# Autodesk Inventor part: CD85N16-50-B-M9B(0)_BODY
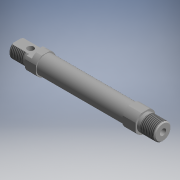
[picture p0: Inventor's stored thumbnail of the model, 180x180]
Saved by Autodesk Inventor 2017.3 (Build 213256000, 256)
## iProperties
Part Number: CD85N16-50-B-M9B(0)_BODY
Material: Generic
Catalog Web Link: www.cadenas.de
Description: C85/CD85 BODY-ISO Standard Air Cylinder:Standard Type Double Acting Single Rod
Vendor: SMC
Document SubType Name: Modeling
Designer: partserver
Manufacturer: SMC
Mass: 19.9773 g
Surface Area: 122.047 cm^2
Volume: 19.9773 cm^3
Density: 1 g/cm^3
Appearance: PSOLRGB-192-192-192
Category: PARTsolutions
Company: SMC
Title: CD85N16-50-B-M9B_BODY
Author: Cadenas PARTsolutions
Comments: ISO Standard Air Cylinder:Standard Type Double Acting Single Rod
PSOL_IDENT_0: {$CADENAS_DATA\23d-libs\smc_jp\actuator\standard_air_cylinder\c85\c85\parts\c85_body.prj},247 {VTYP=
PSOL_IDENT_1: 3D},{NB=CD85N16-50-B-M9B(0)_BODY},{LINA=CD85N16-50-B-M9B_BODY},{NN=C85/CD85 BODY},{DATE=09.12.2020 0
PSOL_IDENT_2: 3:32:12},{GEOMDATE=26.04.2020 06:36:00},{VERSION=},{LINEID=90},{WBVAR=MAGNET,AUTOSW,STROKE,CUSHION,B
PSOL_IDENT_3: OOT,SWITCHMT,THREAD},{WBNUMERIC=STROKE}  {NB=CD85N16-50-B-M9B(0)_BODY},{LINA=CD85N16-50-B-M9B_BODY},
PSOL_IDENT_4: {KT=DUMMY},{ORDER=CD85N16-50-B-M9B},{BORE=16},{MOUNT=(N) Basic (Integral clevis)},{MOUNTX=N},{MAGNET=
PSOL_IDENT_5: D},{AUTOSW=-M9B},{AUTOSWX='','(-) Without auto switch','-M9N','M9N','-M9P','M9P','-M9B','M9B','-M9NV'
PSOL_IDENT_6: ,'M9NV','-M9PV','M9PV','-M9BV','M9BV','-M9NW','M9NW','-M9PW','M9PW','-M9BW','M9BW','-M9NWV','M9NWV','
PSOL_IDENT_7: -M9PWV','M9PWV','-M9BWV','M9BWV','-M9NA','M9NA','-M9PA','M9PA','-M9BA','M9BA','-M9NAV','M9NAV','-M9P
PSOL_IDENT_8: AV','M9PAV','-M9BAV','M9BAV','-A90','A90','-A93','A93','-A96','A96','-A90V','A90V','-A93V','A93V','-
PSOL_IDENT_9: A96V','A96V','-H7C','H7C','-H7NF','H7NF','-C73C','C73C','-C80C','C80C','-J79C','J79C','-F79F','F79F'
PSOL_IDENT_10: ,'-A72','A72','-A72H','A72H','-A73C','A73C','-A80C','A80C','-A79W','A79W'},{STROKE=50},{CUSHION=},{C
PSOL_IDENT_11: USHIONX= '','(-) Rubber bumper(Standard)','C','(C) Air cushion' },{BOOT=},{BOOTX= '','N/A' },{SWITCH
PSOL_IDENT_12: MT=-B},{SWITCHMTX= '-A','(A) Rail mounting','-B','(B) Band mounting' },{THREAD=0},{MAX=400},{MAX1=20
PSOL_IDENT_13: 0},{AM=16},{BE=M16x1.5},{BED=16},{BEJ=1.50},{C=6},{CD=6},{D=19.7},{EE=M5x0.8},{EW=12},{F=17},{G1=8},
PSOL_IDENT_14: {G2=6},{HR=14.0},{N1=12.5},{N2=10.5},{NA=18.3},{ND=16},{RR=13},{S=56},{U=9},{WA=9.5},{D1=17.400},{SW
PSOL_IDENT_15: A=7.5},{SWB=13.5},{SW=2}
NB: CD85N16-50-B-M9B(0)_BODY
NN: C85/CD85 BODY
NT: ISO Standard Air Cylinder:Standard Type Double Acting Single Rod
NBSYN: $ORDER.($THREAD.)_BODY
LINA: CD85N16-50-B-M9B_BODY
CATALOG: SMC (JP
BORE: 16
MOUNT: (N) Basic (Integral clevis)
MAGNET: (D) With magnet
AUTOSW: M9B
STROKE: 50
CUSHION: (-) Rubber bumper(Standard)
BOOT: N/A
SWITCHMT: (B) Band mounting
THREAD: on
MAX: 400
MAX1: 200
AM: 16
BE: M16x1.5
BED: 16
BEJ: 1.5
C: 6
CD: 6
D: 19.7
EE: M5x0.8
EW: 12
F: 17
HR: 14
NA: 18.3
ND: 16
RR: 13
U: 9
WA: 9.5
D1: 17.4
SUPPLIER: SMC
ARTICLENO: CD85N16-50-B-M9B(0)_BODY
BOMINFO: CD85N16-50-B-M9B_BODY
CREATOR: CADENAS GmbH
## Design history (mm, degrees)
sketch "Sketch_1"
  geometry: L1 (106, 0)-(-17, 0); L2 (67.5, 0)-(67.5, 8); L3 (67.5, 8)-(12.5, 8); L4 (12.5, 8)-(12.5, 3); L5 (12.5, 3)-(-17, 3); L6 (-17, 3)-(-17, 7.08); L7 (-17, 7.08)-(-16.08, 8); L8 (-16.08, 8)-(0, 8); L9 (0, 8)-(0, 9.85); L10 (0, 9.85)-(12.5, 9.85); L11 (12.5, 9.85)-(12.5, 8.7); L12 (12.5, 8.7)-(95.5, 8.7); L13 (95.5, 8.7)-(95.5, 9.85); L14 (95.5, 9.85)-(106, 9.85); L15 (106, 9.85)-(106, 0); L16 (106, 0)-(67.5, 0)
  constraints: 32 end point
revolve "Revolution1" sketch "Sketch_1" stored, may be unused: angle "d0" = 360 deg
thread "Thread1" dims "d1" = 13.08, "d2" = 0
sketch "Sketch_2"
  geometry: L1 (3.647, 9.15)-(-3.647, 9.15); L2 (-9.15, 3.647)-(-9.15, -3.647); L3 (-3.647, -9.15)-(3.647, -9.15); L4 (9.15, -3.647)-(9.15, 3.647); C1 r 13.133 at (0, 0); A1 r 9.85 centre (0, 0) between (-3.647, 9.15) and (-9.15, 3.647); A2 r 9.85 centre (0, 0) between (-9.15, -3.647) and (-3.647, -9.15); A3 r 9.85 centre (0, 0) between (3.647, -9.15) and (9.15, -3.647); A4 r 9.85 centre (0, 0) between (9.15, 3.647) and (3.647, 9.15); 1 further point
  constraints: 8 end point, 8 point on circle, 5 centre point
extrude "Extrusion1" cut sketch "Sketch_2" distance "d3" = 111; taper "d4" = 0 deg
sketch "Sketch_3"
  geometry: L1 (8, 4.15)-(8, 9.15); L2 (8, 9.15)-(10.5, 9.15); L3 (10.5, 9.15)-(10.067, 8.717); L4 (10.067, 8.717)-(10.067, 4.15); L5 (10.067, 4.15)-(8, 2.957); L6 (8, 2.957)-(8, 9.15)
  constraints: 12 end point
revolve "Revolution2" sketch "Sketch_3" stored, may be unused: angle "d5" = 360 deg
thread "Thread2" dims "d6" = 4.567, "d7" = 0
sketch "Sketch_5"
  geometry: L1 (100, 4.15)-(100, 9.15); L2 (100, 9.15)-(102.5, 9.15); L3 (102.5, 9.15)-(102.067, 8.717); L4 (102.067, 8.717)-(102.067, 4.15); L5 (102.067, 4.15)-(100, 2.957); L6 (100, 2.957)-(100, 9.15)
  constraints: 12 end point
revolve "Revolution3" sketch "Sketch_5" stored, may be unused: angle "d8" = 360 deg
thread "Thread3" dims "d9" = 4.567, "d10" = 0
sketch "Sketch_13"
  geometry: L1 (123, 0)-(106, 0); L2 (106, 0)-(106, 8); L3 (106, 8)-(122.08, 8); L4 (122.08, 8)-(123, 7.08); L5 (123, 7.08)-(123, 0); L6 (123, 0)-(106, 0)
  constraints: 12 end point
revolve "Revolution4" sketch "Sketch_13" stored, may be unused: angle "d11" = 360 deg
thread "Thread4" dims "d12" = 13.08, "d13" = 0
sketch "Sketch_14"
  geometry: L1 (-101, -9.85)-(-101, -6); L2 (-101, -6)-(-123, -6); L3 (-123, -6)-(-123, 6); L4 (-123, 6)-(-101, 6); L5 (-101, 6)-(-101, 9.85); L6 (-101, 9.85)-(-128, 9.85); L7 (-128, 9.85)-(-128, -9.85); L8 (-128, -9.85)-(-101, -9.85)
  constraints: 16 end point
extrude "Extrusion2" cut sketch "Sketch_14" stored distance "d14" = 19.7; taper "d15" = 0 deg
sketch "Sketch_15"
  geometry: C1 r 3 at (110, 0); 1 further point
  constraints: 1 centre point
extrude "Extrusion3" cut sketch "Sketch_15" stored distance "d16" = 19.7; taper "d17" = 0 deg
node "BODY_XY"
node "BODY_YZ"
node "BODY_ZX"
node "BODY_X"
node "BODY_Y"
node "BODY_Z"
node "BODY_Center"
node "BODY_MNUT_XY"
node "BODY_MNUT_YZ"
node "BODY_MNUT_ZX"
node "BODY_MNUT_X"
node "BODY_MNUT_Y"
node "BODY_MNUT_Z"
node "BODY_MNUT_Center"
node "BODY_MNUT2_XY"
node "BODY_MNUT2_YZ"
node "BODY_MNUT2_ZX"
node "BODY_MNUT2_X"
node "BODY_MNUT2_Y"
node "BODY_MNUT2_Z"
node "BODY_MNUT2_Center"
node "Body_Bracket1_XY"
node "Body_Bracket1_YZ"
node "Body_Bracket1_ZX"
node "Body_Bracket1_X"
node "Body_Bracket1_Y"
node "Body_Bracket1_Z"
node "Body_Bracket1_Center"
node "Body_Bracket2_XY"
node "Body_Bracket2_YZ"
node "Body_Bracket2_ZX"
node "Body_Bracket2_X"
node "Body_Bracket2_Y"
node "Body_Bracket2_Z"
node "Body_Bracket2_Center"
node "Body_Clevis_XY"
node "Body_Clevis_YZ"
node "Body_Clevis_ZX"
node "Body_Clevis_X"
node "Body_Clevis_Y"
node "Body_Clevis_Z"
node "Body_Clevis_Center"
node "Body_SMA_Rail1_XY"
node "Body_SMA_Rail1_YZ"
node "Body_SMA_Rail1_ZX"
node "Body_SMA_Rail1_X"
node "Body_SMA_Rail1_Y"
node "Body_SMA_Rail1_Z"
node "Body_SMA_Rail1_Center"
node "Body_SMB_Rail2_XY"
node "Body_SMB_Rail2_YZ"
node "Body_SMB_Rail2_ZX"
node "Body_SMB_Rail2_X"
node "Body_SMB_Rail2_Y"
node "Body_SMB_Rail2_Z"
node "Body_SMB_Rail2_Center"
node "Body_SWA_Band1_XY"
node "Body_SWA_Band1_YZ"
node "Body_SWA_Band1_ZX"
node "Body_SWA_Band1_X"
node "Body_SWA_Band1_Y"
node "Body_SWA_Band1_Z"
node "Body_SWA_Band1_Center"
node "Body_SWB_Band2_XY"
node "Body_SWB_Band2_YZ"
node "Body_SWB_Band2_ZX"
node "Body_SWB_Band2_X"
node "Body_SWB_Band2_Y"
node "Body_SWB_Band2_Z"
node "Body_SWB_Band2_Center"
node "ND_1_XY"
node "ND_1_YZ"
node "ND_1_ZX"
node "ND_1_X"
node "ND_1_Y"
node "ND_1_Z"
node "ND_1_Center"
node "RR_XY"
node "RR_YZ"
node "RR_ZX"
node "RR_X"
node "RR_Y"
node "RR_Z"
node "RR_Center"
body "Solid1"
other parameters: "d18" = 0, "d19" = 0, "d20" = 0
